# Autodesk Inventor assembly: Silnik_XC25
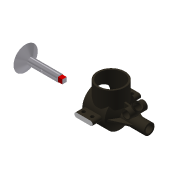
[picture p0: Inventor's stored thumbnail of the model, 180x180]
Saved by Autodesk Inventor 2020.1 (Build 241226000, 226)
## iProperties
Created: 2014-01
Part Number: Silnik_XC25
Document SubType Name: Assembly
Designer: F.Stasiak
Manager: www.cadconsulting.pl
Company: Fabian Stasiak CAD Consulting
Author: F.Stasiak
Subject: Zbiór ćwiczeń. Autodesk Inventor 2020. Kurs podstawowy
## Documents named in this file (9)
- C:\2020_Kurs_podstawowy\R6 Zespoły\Połączenia\Silnik_XC25.iam
- C:\2020_Kurs_podstawowy\R6 Zespoły\Połączenia\Cylinder_II.ipt
- C:\2020_Kurs_podstawowy\R6 Zespoły\Połączenia\Głowica_II.ipt
- C:\2020_Kurs_podstawowy\R6 Zespoły\Połączenia\Korbowód_II.ipt
- C:\2020_Kurs_podstawowy\R6 Zespoły\Połączenia\Korpus_II.ipt
- C:\2020_Kurs_podstawowy\R6 Zespoły\Połączenia\Pokrywa_II.ipt
- C:\2020_Kurs_podstawowy\R6 Zespoły\Połączenia\Swożeń_II.ipt
- C:\2020_Kurs_podstawowy\R6 Zespoły\Połączenia\Tłok_II.ipt
- C:\2020_Kurs_podstawowy\R6 Zespoły\Połączenia\Wałek_II.ipt
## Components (8 placed, 8 different names)
1. Korpus_II:1
2. Wałek_II:1
3. Tłok_II:1
4. Korbowód_II:1
5. Swożeń_II:1
6. Cylinder_II:1
7. Głowica_II:1
8. Pokrywa_II:1
